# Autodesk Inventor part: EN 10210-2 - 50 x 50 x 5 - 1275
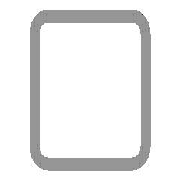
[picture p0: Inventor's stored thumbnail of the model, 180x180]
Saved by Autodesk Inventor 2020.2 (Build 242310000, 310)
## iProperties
Created: 2019-01
Part Number: EN 10210-2 - 50 x 50 x 5 - 1275
Material: Stahl, weich
Description: Rohrleitung
Document SubType Name: Modeling
Standard: DIN
Designer: lutzd
Standard Revision: 2006-07
Standards Organization: DIN
Language: de-DE
Size Designation: 50 x 50 x 5
Categories: <MemberInstance><Categories><Category DisplayName="Profile" InternalName="089c4875-fa83-4c05-b084-43b9cc11f5ed" Mnemonic="GRDR"><CategoryParameter DisplayName="
Stock Number: 50 x 50 x 5
Mass: 8739.39 g
Surface Area: 4333.85 cm^2
Volume: 1113.3 cm^3
Density: 7.85 g/cm^3
Appearance: Semi-Polished(8)
IsCustomPart: 1
G_L: 1275,000 mm
G_W: 50,000 mm
G_H: 50,000 mm
DocNumber: ADSK-014269
Folder: .
Dimensions: 50x50x1275 mm
Mass: 8,739 kg
+54B25884-A07A-4A9D-A59F-DCD10F55025F+SCHNITTDETAIL1: Schnittwinkel 90,00 grd
+6FA9F5F0-B081-49E7-A552-B882687D28F9+SCHNITTDETAIL2: Schnittwinkel 90,00 grd
VLT_Material: Stahl, weich
_CCFamilyMember: 16
_CCFamilyDisplayName: DIN EN 10210-2 (USAS B17.1 quadratisch) - Rohrleitung — In Klammern angegebene Größen wurden aufgehoben
_FrameMemberDoc: Frame Member File
_Version: 15.0.0
_GetPNFromCC: 1
Title: Profil-Bauteil
Author: lutzd
Revision Number: -
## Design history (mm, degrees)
node "Startebene"
node "Endebene"
sketch "Skizze"
  geometry: L1 (-25, -17.5)-(-25, 17.5); L2 (-17.5, 25)-(17.5, 25); L3 (25, 17.5)-(25, -17.5); L4 (17.5, -25)-(-17.5, -25); L5 (-15, 20)-(15, 20); L6 (20, 15)-(20, -15); L7 (15, -20)-(-15, -20); L8 (-20, -15)-(-20, 15); L9 (0, 37.175)-(0, -37.175) reference; L10 (-37.175, 0)-(37.175, 0) reference; A1 r 7.5 centre (-17.5, -17.5) between (-25, -17.5) and (-17.5, -25); A2 r 7.5 centre (-17.5, 17.5) between (-17.5, 25) and (-25, 17.5); A3 r 7.5 centre (17.5, 17.5) between (25, 17.5) and (17.5, 25); A4 r 7.5 centre (17.5, -17.5) between (17.5, -25) and (25, -17.5); A5 r 5 centre (-15, -15) between (-20, -15) and (-15, -20); A6 r 5 centre (-15, 15) between (-15, 20) and (-20, 15); A7 r 5 centre (15, 15) between (20, 15) and (15, 20); A8 r 5 centre (15, -15) between (15, -20) and (20, -15)
  constraints: 16 end point, 16 point on circle, 16 tangent, 8 centre point, 6 equal radius, 4 parallel, 2 perpendicular, 2 other
  dimensions: "d7" = 7.5 radius of A1 (= G_IR); "d10" = 50 distance between parallel lines of L2 L4 (= G_H); "d11" = 50 distance between parallel lines of L1 L3 (= G_W); "d12" = 5 distance between parallel lines of L3 L6 (= G_T); "d15" = 25 distance between parallel lines of L2 L10 (= 0.5 x d10); "d16" = 25 distance between parallel lines of L9 L3 (= 0.5 x d11); "d19" = 5 radius of A5 (= G_T); "d20" = 5 distance between parallel lines of L4 L7 (= G_T)
extrude "Körper" new body sketch "Skizze" stored distance "d3" = 1275 (= G_L); taper "d4" = 0 deg
node "Driven Length"
  sketch "Sketch3"
    geometry: L1 (0, 0)-(10, 0) reference
    constraints: 2 end point, 1 horizontal
  workplane "Work Plane3"
  sketch "Sketch4"
    geometry: L1 (-2, 50)-(12, 50) reference; L2 (-2, 1325)-(12, 1325) reference
    dimensions: "d18" = 1275 distance between parallel lines of L1 L2 (derived)
workplane "Arbeitsebene4"
feature "Trennen1"
workplane "Arbeitsebene5"
feature "Trennen2"
body "Solid1"
other parameters: "G_W" = 50 [user parameter; used in 1 equation term], "G_H" = 50 [user parameter; used in 1 equation term], "G_T" = 5 [user parameter; used in 3 equation terms], "G_IR" = 7.5 [user parameter; used in 1 equation term], "G_L" = 1275 (= d18) [user parameter; used in 1 equation term], "d14" = 1325 (= G_OFFSET_END + B_L), "B_L" = 1375 [user parameter; used in 1 equation term], "d17" = 90 deg
